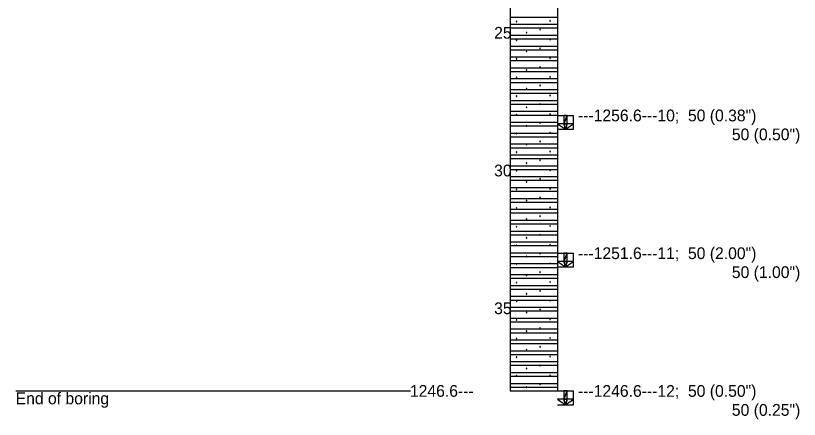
# Model space of a CAD drawing. Extents: x 7 to 126, y 24 to 56.
# Drawn here: x 96.7 to 104.98, y 38.99 to 43.25 of the extents above; entities that cross this region are included whole.
import ezdxf

# ---------------------------------------------------------------- set-up
doc = ezdxf.new("R2010")
doc.units = 0

msp = doc.modelspace()

# ---------------------------------------------------------------- linework, layer by layer
for points in [[(101.9252, 50.3343), (101.9252, 39.2878)], [(102.4252, 50.3343), (102.4252, 39.2878)], [(101.9252, 43.2324), (102.4252, 43.2324)], [(101.9956, 43.1862), (101.9939, 43.189), (101.9907, 43.189), (101.989, 43.1862), (101.9907, 43.1833), (101.9939, 43.1833), (101.9956, 43.1862)], [(102.3483, 43.1927), (102.3467, 43.1955), (102.3434, 43.1955), (102.3418, 43.1927), (102.3434, 43.1898), (102.3467, 43.1898), (102.3483, 43.1927)], [(101.9252, 43.1569), (102.4252, 43.1569)], [(101.9252, 43.1175), (102.4252, 43.1175)], [(102.2428, 43.1001), (102.2412, 43.103), (102.2379, 43.103), (102.2363, 43.1001), (102.2379, 43.0973), (102.2412, 43.0973), (102.2428, 43.1001)], [(101.9252, 43.0421), (102.4252, 43.0421)], [(102.1002, 43.0683), (102.0986, 43.0711), (102.0953, 43.0711), (102.0937, 43.0683), (102.0953, 43.0654), (102.0986, 43.0654), (102.1002, 43.0683)], [(101.9252, 43.0027), (102.4252, 43.0027)], [(101.9956, 42.9893), (101.9939, 42.9921), (101.9907, 42.9921), (101.989, 42.9893), (101.9907, 42.9864), (101.9939, 42.9864), (101.9956, 42.9893)], [(102.3483, 42.9958), (102.3467, 42.9987), (102.3434, 42.9987), (102.3418, 42.9958), (102.3434, 42.993), (102.3467, 42.993), (102.3483, 42.9958)], [(101.9252, 42.9272), (102.4252, 42.9272)], [(101.9252, 42.8879), (102.4252, 42.8879)], [(102.1002, 42.8714), (102.0986, 42.8743), (102.0953, 42.8743), (102.0937, 42.8715), (102.0953, 42.8686), (102.0986, 42.8686), (102.1002, 42.8714)], [(102.2428, 42.9033), (102.2412, 42.9061), (102.2379, 42.9061), (102.2363, 42.9033), (102.2379, 42.9005), (102.2412, 42.9005), (102.2428, 42.9033)], [(101.9252, 42.8124), (102.4252, 42.8124)], [(101.9252, 42.773), (102.4252, 42.773)], [(101.9956, 42.7925), (101.9939, 42.7953), (101.9907, 42.7953), (101.989, 42.7925), (101.9907, 42.7896), (101.9939, 42.7896), (101.9956, 42.7925)], [(102.3483, 42.799), (102.3467, 42.8018), (102.3434, 42.8018), (102.3418, 42.799), (102.3434, 42.7961), (102.3467, 42.7961), (102.3483, 42.799)], [(101.9252, 42.6976), (102.4252, 42.6976)], [(102.2428, 42.7064), (102.2412, 42.7093), (102.2379, 42.7093), (102.2363, 42.7064), (102.2379, 42.7036), (102.2412, 42.7036), (102.2428, 42.7064)], [(101.9252, 42.6582), (102.4252, 42.6582)], [(102.1002, 42.6746), (102.0986, 42.6774), (102.0953, 42.6774), (102.0937, 42.6746), (102.0953, 42.6717), (102.0986, 42.6717), (102.1002, 42.6746)], [(102.3483, 42.6021), (102.3467, 42.605), (102.3434, 42.605), (102.3418, 42.6021), (102.3434, 42.5993), (102.3467, 42.5993), (102.3483, 42.6021)], [(101.9252, 42.5828), (102.4252, 42.5828)], [(101.9252, 42.5434), (102.4252, 42.5434)], [(101.9956, 42.5956), (101.9939, 42.5984), (101.9907, 42.5984), (101.989, 42.5956), (101.9907, 42.5927), (101.9939, 42.5927), (101.9956, 42.5956)], [(101.9252, 42.4679), (102.4252, 42.4679)], [(102.1002, 42.4777), (102.0986, 42.4806), (102.0953, 42.4806), (102.0937, 42.4778), (102.0953, 42.4749), (102.0986, 42.4749), (102.1002, 42.4777)], [(102.2428, 42.5096), (102.2412, 42.5124), (102.2379, 42.5124), (102.2363, 42.5096), (102.2379, 42.5068), (102.2412, 42.5068), (102.2428, 42.5096)], [(101.9252, 42.4286), (102.4252, 42.4286)], [(101.9956, 42.3988), (101.9939, 42.4016), (101.9907, 42.4016), (101.989, 42.3988), (101.9907, 42.3959), (101.9939, 42.3959), (101.9956, 42.3988)], [(102.3483, 42.4053), (102.3467, 42.4081), (102.3434, 42.4081), (102.3418, 42.4053), (102.3434, 42.4024), (102.3467, 42.4024), (102.3483, 42.4053)], [(101.9252, 42.3531), (102.4252, 42.3531)], [(101.9252, 42.3137), (102.4252, 42.3137)], [(102.1002, 42.2809), (102.0986, 42.2837), (102.0953, 42.2837), (102.0937, 42.2809), (102.0953, 42.278), (102.0986, 42.278), (102.1002, 42.2809)], [(102.2428, 42.3127), (102.2412, 42.3156), (102.2379, 42.3156), (102.2363, 42.3127), (102.2379, 42.3099), (102.2412, 42.3099), (102.2428, 42.3127)], [(101.9252, 42.2383), (102.4252, 42.2383)], [(101.9252, 42.1989), (102.4252, 42.1989)], [(101.9956, 42.2019), (101.9939, 42.2047), (101.9907, 42.2047), (101.989, 42.2019), (101.9907, 42.199), (101.9939, 42.199), (101.9956, 42.2019)], [(102.3483, 42.2084), (102.3467, 42.2113), (102.3434, 42.2113), (102.3418, 42.2084), (102.3434, 42.2056), (102.3467, 42.2056), (102.3483, 42.2084)], [(102.4252, 42.1948), (102.5918, 42.1948)], [(102.5918, 42.0494), (102.5918, 42.1948)], [(101.9252, 42.1234), (102.4252, 42.1234)], [(102.2428, 42.1159), (102.2412, 42.1187), (102.2379, 42.1187), (102.2363, 42.1159), (102.2379, 42.1131), (102.2412, 42.1131), (102.2428, 42.1159)], [(101.9252, 42.0841), (102.4252, 42.0841)], [(102.1002, 42.084), (102.0986, 42.0869), (102.0953, 42.0869), (102.0937, 42.0841), (102.0953, 42.0812), (102.0986, 42.0812), (102.1002, 42.084)], [(102.4252, 42.0494), (102.5918, 42.0494)], [(101.9252, 42.0086), (102.4252, 42.0086)], [(101.9252, 41.9692), (102.4252, 41.9692)], [(101.9956, 42.0051), (101.9939, 42.0079), (101.9907, 42.0079), (101.989, 42.0051), (101.9907, 42.0022), (101.9939, 42.0022), (101.9956, 42.0051)], [(102.3483, 42.0116), (102.3467, 42.0144), (102.3434, 42.0144), (102.3418, 42.0116), (102.3434, 42.0087), (102.3467, 42.0087), (102.3483, 42.0116)], [(101.9252, 41.8938), (102.4252, 41.8938)], [(102.1002, 41.8872), (102.0986, 41.89), (102.0953, 41.89), (102.0937, 41.8872), (102.0953, 41.8843), (102.0986, 41.8843), (102.1002, 41.8872)], [(102.2428, 41.919), (102.2412, 41.9219), (102.2379, 41.9219), (102.2363, 41.919), (102.2379, 41.9162), (102.2412, 41.9162), (102.2428, 41.919)], [(101.9252, 41.8544), (102.4252, 41.8544)], [(101.9252, 41.7789), (102.4252, 41.7789)], [(101.9956, 41.8082), (101.9939, 41.811), (101.9907, 41.811), (101.989, 41.8082), (101.9907, 41.8053), (101.9939, 41.8053), (101.9956, 41.8082)], [(102.3483, 41.8147), (102.3467, 41.8176), (102.3434, 41.8176), (102.3418, 41.8147), (102.3434, 41.8119), (102.3467, 41.8119), (102.3483, 41.8147)], [(101.9252, 41.7396), (102.4252, 41.7396)], [(102.2428, 41.7222), (102.2412, 41.725), (102.2379, 41.725), (102.2363, 41.7222), (102.2379, 41.7194), (102.2412, 41.7194), (102.2428, 41.7222)], [(101.9252, 41.6641), (102.4252, 41.6641)], [(101.9252, 41.6247), (102.4252, 41.6247)], [(101.9956, 41.6114), (101.9939, 41.6142), (101.9907, 41.6142), (101.989, 41.6114), (101.9907, 41.6085), (101.9939, 41.6085), (101.9956, 41.6114)], [(102.1002, 41.6903), (102.0986, 41.6932), (102.0953, 41.6932), (102.0937, 41.6904), (102.0953, 41.6875), (102.0986, 41.6875), (102.1002, 41.6903)], [(102.3483, 41.6179), (102.3467, 41.6207), (102.3434, 41.6207), (102.3418, 41.6179), (102.3434, 41.615), (102.3467, 41.615), (102.3483, 41.6179)], [(101.9252, 41.5493), (102.4252, 41.5493)], [(102.2428, 41.5253), (102.2412, 41.5282), (102.2379, 41.5282), (102.2363, 41.5253), (102.2379, 41.5225), (102.2412, 41.5225), (102.2428, 41.5253)], [(101.9252, 41.5099), (102.4252, 41.5099)], [(102.1002, 41.4934), (102.0986, 41.4963), (102.0953, 41.4963), (102.0937, 41.4935), (102.0953, 41.4906), (102.0986, 41.4906), (102.1002, 41.4934)], [(101.9252, 41.4345), (102.4252, 41.4345)], [(101.9252, 41.3951), (102.4252, 41.3951)], [(101.9956, 41.4145), (101.9939, 41.4173), (101.9907, 41.4173), (101.989, 41.4145), (101.9907, 41.4116), (101.9939, 41.4116), (101.9956, 41.4145)], [(102.3483, 41.421), (102.3467, 41.4239), (102.3434, 41.4239), (102.3418, 41.421), (102.3434, 41.4182), (102.3467, 41.4182), (102.3483, 41.421)], [(101.9252, 41.3196), (102.4252, 41.3196)], [(101.9252, 41.2803), (102.4252, 41.2803)], [(102.1002, 41.2966), (102.0986, 41.2995), (102.0953, 41.2995), (102.0937, 41.2967), (102.0953, 41.2938), (102.0986, 41.2938), (102.1002, 41.2966)], [(102.2428, 41.3285), (102.2412, 41.3313), (102.2379, 41.3313), (102.2363, 41.3285), (102.2379, 41.3257), (102.2412, 41.3257), (102.2428, 41.3285)], [(101.9252, 41.2048), (102.4252, 41.2048)], [(101.9956, 41.2177), (101.9939, 41.2205), (101.9907, 41.2205), (101.989, 41.2177), (101.9907, 41.2148), (101.9939, 41.2148), (101.9956, 41.2177)], [(102.3483, 41.2242), (102.3467, 41.227), (102.3434, 41.227), (102.3418, 41.2242), (102.3434, 41.2213), (102.3467, 41.2213), (102.3483, 41.2242)], [(101.9252, 41.1654), (102.4252, 41.1654)], [(102.2428, 41.1316), (102.2412, 41.1345), (102.2379, 41.1345), (102.2363, 41.1316), (102.2379, 41.1288), (102.2412, 41.1288), (102.2428, 41.1316)], [(101.9252, 41.09), (102.4252, 41.09)], [(101.9252, 41.0506), (102.4252, 41.0506)], [(102.1002, 41.0997), (102.0986, 41.1026), (102.0953, 41.1026), (102.0937, 41.0998), (102.0953, 41.0969), (102.0986, 41.0969), (102.1002, 41.0997)], [(101.9252, 40.9751), (102.4252, 40.9751)], [(101.9956, 41.0208), (101.9939, 41.0236), (101.9907, 41.0236), (101.989, 41.0208), (101.9907, 41.0179), (101.9939, 41.0179), (101.9956, 41.0208)], [(102.3483, 41.0273), (102.3467, 41.0302), (102.3434, 41.0302), (102.3418, 41.0273), (102.3434, 41.0245), (102.3467, 41.0245), (102.3483, 41.0273)], [(101.9252, 40.9358), (102.4252, 40.9358)], [(102.1002, 40.9029), (102.0986, 40.9058), (102.0953, 40.9058), (102.0937, 40.903), (102.0953, 40.9001), (102.0986, 40.9001), (102.1002, 40.9029)], [(102.2428, 40.9348), (102.2412, 40.9376), (102.2379, 40.9376), (102.2363, 40.9348), (102.2379, 40.932), (102.2412, 40.932), (102.2428, 40.9348)], [(101.9252, 40.8603), (102.4252, 40.8603)], [(101.9252, 40.8209), (102.4252, 40.8209)], [(101.9956, 40.824), (101.9939, 40.8268), (101.9907, 40.8268), (101.989, 40.824), (101.9907, 40.8211), (101.9939, 40.8211), (101.9956, 40.824)], [(102.3483, 40.8305), (102.3467, 40.8333), (102.3434, 40.8333), (102.3418, 40.8305), (102.3434, 40.8276), (102.3467, 40.8276), (102.3483, 40.8305)], [(101.9252, 40.7455), (102.4252, 40.7455)], [(101.9252, 40.7061), (102.4252, 40.7061)], [(102.1002, 40.706), (102.0986, 40.7089), (102.0953, 40.7089), (102.0937, 40.7061), (102.0953, 40.7032), (102.0986, 40.7032), (102.1002, 40.706)], [(102.2428, 40.7379), (102.2412, 40.7408), (102.2379, 40.7408), (102.2363, 40.7379), (102.2379, 40.7351), (102.2412, 40.7351), (102.2428, 40.7379)], [(102.4252, 40.7413), (102.5918, 40.7413)], [(102.5918, 40.5959), (102.5918, 40.7413)], [(101.9252, 40.6307), (102.4252, 40.6307)], [(101.9956, 40.6271), (101.9939, 40.6299), (101.9907, 40.6299), (101.989, 40.6271), (101.9907, 40.6242), (101.9939, 40.6242), (101.9956, 40.6271)], [(102.3483, 40.6336), (102.3467, 40.6365), (102.3434, 40.6365), (102.3418, 40.6336), (102.3434, 40.6308), (102.3467, 40.6308), (102.3483, 40.6336)], [(101.9252, 40.5913), (102.4252, 40.5913)], [(102.2428, 40.5411), (102.2412, 40.5439), (102.2379, 40.5439), (102.2363, 40.5411), (102.2379, 40.5383), (102.2412, 40.5383), (102.2428, 40.5411)], [(102.4252, 40.5959), (102.5918, 40.5959)], [(101.9252, 40.5158), (102.4252, 40.5158)], [(101.9252, 40.4765), (102.4252, 40.4765)], [(102.1002, 40.5092), (102.0986, 40.5121), (102.0953, 40.5121), (102.0937, 40.5093), (102.0953, 40.5064), (102.0986, 40.5064), (102.1002, 40.5092)], [(101.9252, 40.401), (102.4252, 40.401)], [(101.9956, 40.4303), (101.9939, 40.4331), (101.9907, 40.4331), (101.989, 40.4303), (101.9907, 40.4274), (101.9939, 40.4274), (101.9956, 40.4303)], [(102.3483, 40.4368), (102.3467, 40.4396), (102.3434, 40.4396), (102.3418, 40.4368), (102.3434, 40.4339), (102.3467, 40.4339), (102.3483, 40.4368)], [(101.9252, 40.3616), (102.4252, 40.3616)], [(102.1002, 40.3123), (102.0986, 40.3152), (102.0953, 40.3152), (102.0937, 40.3124), (102.0953, 40.3095), (102.0986, 40.3095), (102.1002, 40.3123)], [(102.2428, 40.3442), (102.2412, 40.3471), (102.2379, 40.3471), (102.2363, 40.3442), (102.2379, 40.3414), (102.2412, 40.3414), (102.2428, 40.3442)], [(101.9252, 40.2862), (102.4252, 40.2862)], [(101.9252, 40.2468), (102.4252, 40.2468)], [(101.9956, 40.2334), (101.9939, 40.2362), (101.9907, 40.2362), (101.989, 40.2334), (101.9907, 40.2305), (101.9939, 40.2305), (101.9956, 40.2334)], [(102.3483, 40.2399), (102.3467, 40.2428), (102.3434, 40.2428), (102.3418, 40.2399), (102.3434, 40.2371), (102.3467, 40.2371), (102.3483, 40.2399)], [(101.9252, 40.1713), (102.4252, 40.1713)], [(101.9252, 40.132), (102.4252, 40.132)], [(102.2428, 40.1474), (102.2412, 40.1502), (102.2379, 40.1502), (102.2363, 40.1474), (102.2379, 40.1446), (102.2412, 40.1446), (102.2428, 40.1474)], [(101.9252, 40.0565), (102.4252, 40.0565)], [(101.9956, 40.0366), (101.9939, 40.0394), (101.9907, 40.0394), (101.989, 40.0366), (101.9907, 40.0337), (101.9939, 40.0337), (101.9956, 40.0366)], [(102.1002, 40.1155), (102.0986, 40.1184), (102.0953, 40.1184), (102.0937, 40.1156), (102.0953, 40.1127), (102.0986, 40.1127), (102.1002, 40.1155)], [(102.3483, 40.0431), (102.3467, 40.0459), (102.3434, 40.0459), (102.3418, 40.0431), (102.3434, 40.0402), (102.3467, 40.0402), (102.3483, 40.0431)], [(101.9252, 40.0171), (102.4252, 40.0171)], [(101.9252, 39.9417), (102.4252, 39.9417)], [(101.9252, 39.9023), (102.4252, 39.9023)], [(102.1002, 39.9186), (102.0986, 39.9215), (102.0953, 39.9215), (102.0937, 39.9187), (102.0953, 39.9158), (102.0986, 39.9158), (102.1002, 39.9186)], [(102.2428, 39.9505), (102.2412, 39.9534), (102.2379, 39.9534), (102.2363, 39.9505), (102.2379, 39.9477), (102.2412, 39.9477), (102.2428, 39.9505)], [(101.9252, 39.8268), (102.4252, 39.8268)], [(101.9956, 39.8397), (101.9939, 39.8425), (101.9907, 39.8425), (101.989, 39.8397), (101.9907, 39.8368), (101.9939, 39.8368), (101.9956, 39.8397)], [(102.3483, 39.8462), (102.3467, 39.8491), (102.3434, 39.8491), (102.3418, 39.8462), (102.3434, 39.8434), (102.3467, 39.8434), (102.3483, 39.8462)], [(101.9252, 39.7875), (102.4252, 39.7875)], [(101.9252, 39.712), (102.4252, 39.712)], [(102.1002, 39.7218), (102.0986, 39.7247), (102.0953, 39.7247), (102.0937, 39.7219), (102.0953, 39.719), (102.0986, 39.719), (102.1002, 39.7218)], [(102.2428, 39.7537), (102.2412, 39.7565), (102.2379, 39.7565), (102.2363, 39.7537), (102.2379, 39.7509), (102.2412, 39.7509), (102.2428, 39.7537)], [(101.9252, 39.6726), (102.4252, 39.6726)], [(101.9956, 39.6429), (101.9939, 39.6457), (101.9907, 39.6457), (101.989, 39.6429), (101.9907, 39.64), (101.9939, 39.64), (101.9956, 39.6429)], [(102.3483, 39.6494), (102.3467, 39.6522), (102.3434, 39.6522), (102.3418, 39.6494), (102.3434, 39.6465), (102.3467, 39.6465), (102.3483, 39.6494)], [(101.9252, 39.5972), (102.4252, 39.5972)], [(101.9252, 39.5578), (102.4252, 39.5578)], [(102.2428, 39.5568), (102.2412, 39.5597), (102.2379, 39.5597), (102.2363, 39.5568), (102.2379, 39.554), (102.2412, 39.554), (102.2428, 39.5568)], [(101.9252, 39.4824), (102.4252, 39.4824)], [(102.1002, 39.5249), (102.0986, 39.5278), (102.0953, 39.5278), (102.0937, 39.525), (102.0953, 39.5221), (102.0986, 39.5221), (102.1002, 39.5249)], [(101.9252, 39.443), (102.4252, 39.443)], [(101.9956, 39.446), (101.9939, 39.4488), (101.9907, 39.4488), (101.989, 39.446), (101.9907, 39.4431), (101.9939, 39.4431), (101.9956, 39.446)], [(102.3483, 39.4525), (102.3467, 39.4554), (102.3434, 39.4554), (102.3418, 39.4525), (102.3434, 39.4497), (102.3467, 39.4497), (102.3483, 39.4525)], [(101.9252, 39.3675), (102.4252, 39.3675)], [(101.9252, 39.3282), (102.4252, 39.3282)], [(102.1002, 39.3281), (102.0986, 39.331), (102.0953, 39.331), (102.0937, 39.3282), (102.0953, 39.3253), (102.0986, 39.3253), (102.1002, 39.3281)], [(102.2428, 39.36), (102.2412, 39.3628), (102.2379, 39.3628), (102.2363, 39.36), (102.2379, 39.3572), (102.2412, 39.3572), (102.2428, 39.36)], [(96.7039, 39.2878), (100.8706, 39.2878)], [(101.9252, 39.2878), (102.4252, 39.2878)], [(102.4252, 39.2878), (102.5918, 39.2878)], [(102.5918, 39.1425), (102.5918, 39.2878)], [(102.4252, 39.1425), (102.5918, 39.1425)]]:
    msp.add_lwpolyline(points)
for points in [[(102.4918, 42.1076), (102.5252, 42.1076), (102.5252, 42.1948), (102.4918, 42.1076)], [(102.4918, 42.1076), (102.5252, 42.1948), (102.4918, 42.1948), (102.4918, 42.1076)], [(102.4918, 42.1076), (102.4252, 42.1076), (102.5085, 42.0494), (102.4918, 42.1076)], [(102.4918, 42.1076), (102.5085, 42.0494), (102.5252, 42.1076), (102.4918, 42.1076)], [(102.5085, 42.0494), (102.5918, 42.1076), (102.5252, 42.1076), (102.5085, 42.0494)], [(102.4918, 40.6541), (102.5252, 40.6541), (102.5252, 40.7413), (102.4918, 40.6541)], [(102.4918, 40.6541), (102.5252, 40.7413), (102.4918, 40.7413), (102.4918, 40.6541)], [(102.4918, 40.6541), (102.4252, 40.6541), (102.5085, 40.5959), (102.4918, 40.6541)], [(102.4918, 40.6541), (102.5085, 40.5959), (102.5252, 40.6541), (102.4918, 40.6541)], [(102.5085, 40.5959), (102.5918, 40.6541), (102.5252, 40.6541), (102.5085, 40.5959)], [(102.4918, 39.2006), (102.5252, 39.2006), (102.5252, 39.2878), (102.4918, 39.2006)], [(102.4918, 39.2006), (102.5252, 39.2878), (102.4918, 39.2878), (102.4918, 39.2006)], [(102.4918, 39.2006), (102.4252, 39.2006), (102.5085, 39.1425), (102.4918, 39.2006)], [(102.4918, 39.2006), (102.5085, 39.1425), (102.5252, 39.2006), (102.4918, 39.2006)], [(102.5085, 39.1425), (102.5918, 39.2006), (102.5252, 39.2006), (102.5085, 39.1425)]]:
    msp.add_lwpolyline(points, close=True)

# ---------------------------------------------------------------- texts
for s, p in [('25', (101.7548, 43.0049)), ('---1256.6---10;  50 (0.38")', (102.6398, 42.1324)), ('50 (0.50")', (104.2642, 41.9324)), ('30', (101.7548, 41.5514)), ('---1251.6---11;  50 (2.00")', (102.6398, 40.6789)), ('50 (1.00")', (104.2642, 40.4789)), ('35', (101.7548, 40.0979)), ('1246.6---', (100.8657, 39.2258)), ('---1246.6---12;  50 (0.50")', (102.6398, 39.2254)), ('End of boring', (96.7039, 39.1471)), ('50 (0.25")', (104.2642, 39.0254))]:
    msp.add_text(s, height=0.124).set_placement(p)

doc.saveas('drawing.dxf')
